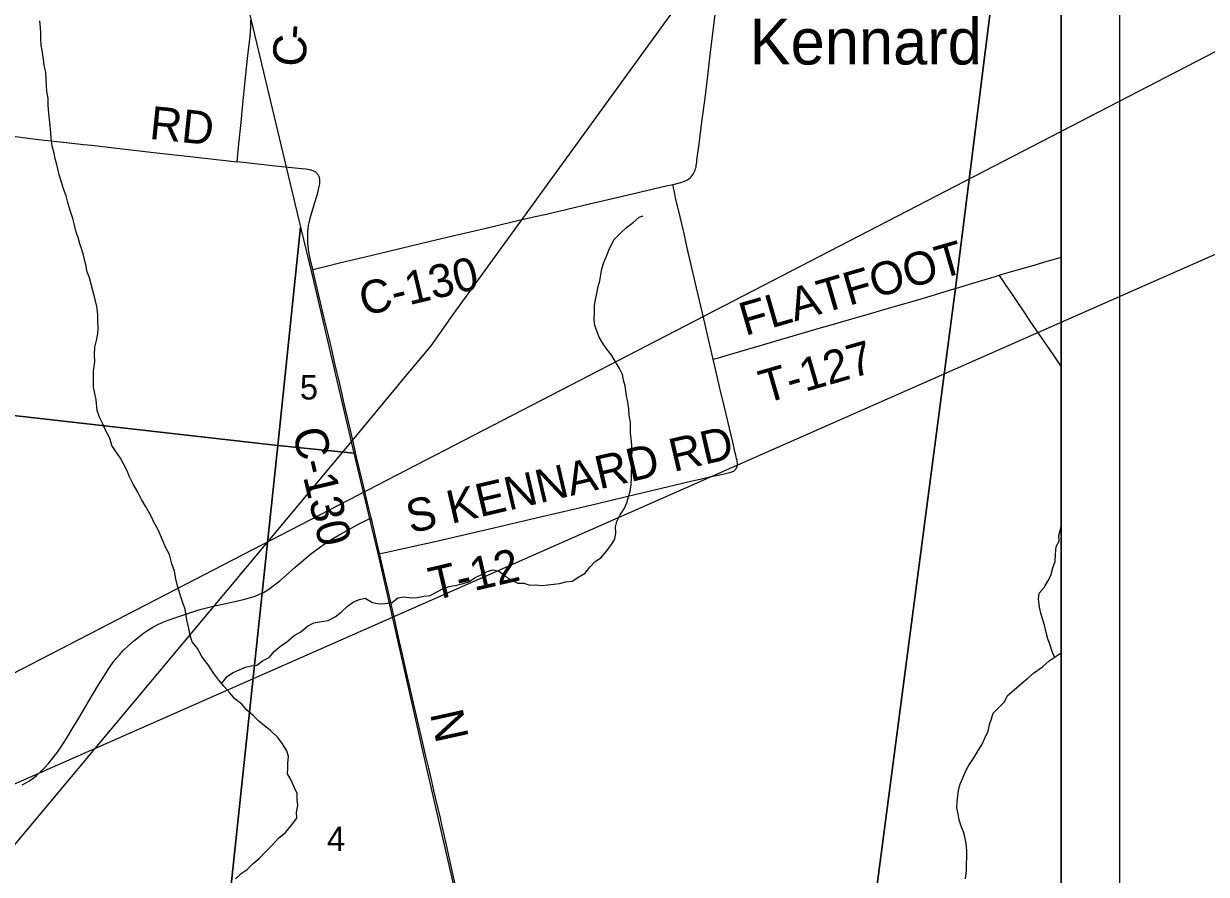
# Model space of a CAD drawing. Extents: x 831 to 1552, y 430 to 870.
# Drawn here: x 1046.09 to 1086.76, y 695.8 to 725.05 of the extents above; entities that cross this region are included whole.
import ezdxf

# ---------------------------------------------------------------- set-up
doc = ezdxf.new("R2010")
doc.units = 0
for name, color, linetype in [('GM_X_Corporation', 7, 'Continuous'), ('GM_X_County_Road', 7, 'Continuous'), ('GM_X_County_Road_Text', 7, 'Continuous'), ('GM_X_Minor_River', 7, 'Continuous'), ('GM_X_Rail_Line', 7, 'Continuous'), ('GM_X_Section_Text', 7, 'Continuous'), ('GM_X_Township_Road', 7, 'Continuous'), ('GM_X_Township_Road_Text', 7, 'Continuous'), ('GM_X_Unincorporated_Text', 7, 'Continuous'), ('SH_Data', 7, 'Continuous'), ('SH_Text', 7, 'Continuous')]:
    doc.layers.add(name, color=color, linetype=linetype)

msp = doc.modelspace()

# ---------------------------------------------------------------- linework, layer by layer
at = {"layer": 'GM_X_Corporation'}
msp.add_lwpolyline([(957.479, 781.045), (956.56, 771.006), (955.451, 760.717), (953.653, 740.871), (952.689, 730.885), (949.971, 703.401), (947.763, 681.071), (945.766, 658.183), (945.766, 650.938), (1069.909, 650.938), (1070.34, 654.531), (1072.813, 675.454), (1078.126, 715.958), (1081.227, 740.59), (1081.766, 744.853), (1081.766, 786.938)], dxfattribs=at)
for points in [[(1069.909, 650.938), (1081.766, 650.938), (1081.766, 744.853), (1081.227, 740.59), (1078.126, 715.958), (1072.813, 675.454), (1070.34, 654.531)], [(1036.878, 732.803), (1052.432, 731.297), (1052.759, 730.026), (1055.607, 718.06), (1054.834, 710.548), (1034.738, 712.834)], [(1056.005, 716.407), (1057.444, 710.279), (1054.834, 710.548), (1055.607, 718.06)], [(1034.738, 712.834), (1054.834, 710.548), (1052.831, 691.774), (1032.694, 693.772)], [(1054.834, 710.548), (1057.444, 710.279), (1058.309, 706.633), (1059.895, 699.645), (1061.888, 690.989), (1052.831, 691.774)]]:
    msp.add_lwpolyline(points, close=True, dxfattribs=at)
at = {"layer": 'GM_X_County_Road'}
for points in [[(1053.43, 720.304), (1053.489, 720.919), (1053.565, 721.652), (1053.631, 722.295), (1053.73, 723.309), (1053.791, 723.852), (1053.845, 724.334), (1053.873, 724.606), (1053.899, 724.929), (1053.905, 725.178)], [(1068.419, 719.528), (1068.685, 719.597), (1068.809, 719.634), (1068.864, 719.657), (1068.919, 719.685), (1068.967, 719.721), (1069.003, 719.75), (1069.04, 719.786), (1069.076, 719.827), (1069.109, 719.876), (1069.135, 719.921), (1069.159, 719.972), (1069.18, 720.024), (1069.197, 720.078), (1069.21, 720.121), (1069.219, 720.174), (1069.233, 720.274), (1069.242, 720.36), (1069.326, 720.996), (1069.414, 721.675), (1069.519, 722.489), (1069.614, 723.254), (1069.689, 723.883), (1069.77, 724.549), (1069.884, 725.449)], [(1056.029, 716.596), (1055.967, 716.862), (1055.921, 717.08), (1055.885, 717.3), (1055.873, 717.4), (1055.862, 717.509), (1055.856, 717.657), (1055.856, 717.792), (1055.862, 717.898), (1055.871, 718.001), (1055.887, 718.112), (1055.905, 718.208), (1055.941, 718.365), (1055.993, 718.556), (1056.11, 718.936), (1056.2, 719.234), (1056.232, 719.355), (1056.25, 719.437), (1056.263, 719.502), (1056.27, 719.555), (1056.273, 719.596), (1056.275, 719.631), (1056.273, 719.668), (1056.271, 719.697), (1056.268, 719.721), (1056.263, 719.745), (1056.255, 719.77), (1056.247, 719.794), (1056.237, 719.818), (1056.227, 719.837), (1056.213, 719.857), (1056.199, 719.877), (1056.186, 719.893), (1056.169, 719.909), (1056.132, 719.942), (1056.11, 719.957), (1056.089, 719.97), (1056.064, 719.983), (1056.041, 719.993), (1056.014, 720.002), (1055.991, 720.01), (1055.961, 720.017), (1055.928, 720.024), (1055.859, 720.036), (1055.778, 720.047), (1055.658, 720.064), (1055.536, 720.078), (1054.855, 720.146), (1053.43, 720.304)], [(1056.029, 716.596), (1056.212, 716.642), (1056.453, 716.704), (1056.996, 716.837), (1057.83, 717.039), (1058.361, 717.166), (1060.065, 717.577), (1060.997, 717.795), (1062.038, 718.036), (1062.884, 718.236), (1063.575, 718.394), (1064.108, 718.514), (1064.773, 718.672), (1065.548, 718.853), (1066.491, 719.076), (1067.313, 719.272), (1068.185, 719.473), (1068.419, 719.528)], [(1058.04, 708.056), (1057.918, 708.564), (1057.773, 709.158), (1057.54, 710.148), (1057.44, 710.583), (1057.292, 711.225), (1057.113, 711.986), (1056.956, 712.665), (1056.804, 713.318), (1056.683, 713.851), (1056.579, 714.287), (1056.423, 714.927), (1056.248, 715.664), (1056.029, 716.596)], [(1046.033, 698.877), (1046.19, 698.956), (1046.285, 699.016), (1046.378, 699.08), (1046.46, 699.144), (1046.535, 699.204), (1046.685, 699.337), (1046.817, 699.469), (1046.943, 699.608), (1047.086, 699.781), (1047.214, 699.95), (1047.356, 700.154), (1047.558, 700.468), (1047.817, 700.893), (1047.949, 701.118), (1048.188, 701.525), (1048.639, 702.283), (1048.819, 702.566), (1048.925, 702.734), (1049.033, 702.9), (1049.147, 703.062), (1049.268, 703.219), (1049.38, 703.35), (1049.516, 703.493), (1049.677, 703.648), (1049.872, 703.821), (1050.034, 703.954), (1050.212, 704.089), (1050.384, 704.209), (1050.531, 704.3), (1050.684, 704.381), (1050.852, 704.458), (1051.024, 704.528), (1051.293, 704.623), (1051.634, 704.738), (1052.011, 704.863), (1052.189, 704.917), (1052.333, 704.955), (1052.562, 705.011), (1053.253, 705.164), (1053.69, 705.263), (1053.895, 705.318), (1054.049, 705.369), (1054.2, 705.43), (1054.335, 705.496), (1054.455, 705.565), (1054.57, 705.64), (1054.72, 705.752), (1054.894, 705.894), (1055.091, 706.065), (1055.426, 706.361), (1055.791, 706.677), (1055.955, 706.808), (1056.262, 707.04), (1056.454, 707.176), (1056.629, 707.292), (1056.909, 707.452), (1057.559, 707.816), (1057.83, 707.955), (1058.04, 708.056)], [(1058.323, 706.828), (1058.243, 707.172), (1058.069, 707.936), (1058.04, 708.056)], [(1061.073, 694.835), (1060.978, 695.259), (1060.802, 696.022), (1060.658, 696.652), (1060.492, 697.405), (1060.418, 697.732), (1060.343, 698.059), (1060.196, 698.687), (1060.121, 699.001), (1060.016, 699.448), (1059.92, 699.859), (1059.759, 700.562), (1059.599, 701.252), (1059.507, 701.639), (1059.434, 701.954), (1059.313, 702.487), (1059.125, 703.311), (1059.017, 703.796), (1058.85, 704.535), (1058.736, 705.044), (1058.632, 705.504), (1058.458, 706.242), (1058.323, 706.828)]]:
    msp.add_lwpolyline(points, dxfattribs=at)
at = {"layer": 'GM_X_Minor_River'}
for points in [[(1054.171, 701.072), (1053.975, 701.279), (1053.764, 701.449), (1053.59, 701.648), (1053.348, 701.84), (1053.175, 702.04), (1052.987, 702.262), (1052.798, 702.477), (1052.633, 702.706), (1052.468, 702.959), (1052.22, 703.296), (1052.07, 703.563), (1051.889, 703.801), (1051.815, 704.014), (1051.771, 704.25), (1051.698, 704.555), (1051.64, 704.92), (1051.559, 705.134), (1051.492, 705.347), (1051.381, 705.72), (1051.323, 705.964), (1051.272, 706.223), (1051.183, 706.482), (1051.102, 706.794), (1050.982, 707.031), (1050.848, 707.328), (1050.714, 707.649), (1050.579, 707.893), (1050.467, 708.137), (1050.28, 708.458), (1050.137, 708.695), (1050.01, 708.947), (1049.86, 709.214), (1049.725, 709.466), (1049.644, 709.672), (1049.524, 709.916), (1049.419, 710.114), (1049.254, 710.344), (1049.119, 710.543), (1049.052, 710.794), (1048.888, 711.099), (1048.798, 711.32), (1048.701, 711.518), (1048.612, 711.747), (1048.585, 712.119), (1048.49, 712.553), (1048.487, 713.107), (1048.536, 713.425), (1048.523, 713.661), (1048.533, 713.934), (1048.589, 714.153), (1048.644, 714.388), (1048.646, 714.593), (1048.64, 714.828), (1048.635, 715.048), (1048.607, 715.322), (1048.556, 715.527), (1048.35, 716.318), (1048.275, 716.516), (1048.232, 716.76), (1048.144, 717.087), (1048.085, 717.285), (1048.018, 717.482), (1047.959, 717.695), (1047.9, 717.886), (1047.841, 718.121), (1047.775, 718.35), (1047.686, 718.631), (1047.612, 718.898), (1047.554, 719.133), (1047.464, 719.369), (1047.39, 719.605), (1047.309, 719.856), (1047.229, 720.214), (1047.177, 720.404), (1047.133, 720.601), (1047.075, 720.845), (1047.039, 721.111), (1047.026, 721.316), (1046.997, 721.536), (1046.956, 721.976), (1046.935, 722.235), (1046.93, 722.477), (1046.887, 722.728), (1046.873, 722.918), (1046.867, 723.13), (1046.847, 723.381), (1046.796, 723.617), (1046.767, 723.837), (1046.724, 724.126), (1046.696, 724.316), (1046.683, 724.543), (1046.677, 724.733), (1046.663, 724.923), (1046.65, 725.151)], [(1065.717, 715.365), (1065.749, 715.554), (1065.804, 715.774), (1065.845, 716.016), (1065.9, 716.213), (1065.932, 716.426), (1065.972, 716.623), (1066.043, 716.835), (1066.159, 717.114), (1066.23, 717.326), (1066.393, 717.636), (1066.623, 717.862), (1066.823, 718.042), (1067.053, 718.215), (1067.253, 718.395), (1067.39, 718.447)], [(1052.896, 702.366), (1053.097, 702.611), (1053.288, 702.746), (1053.502, 702.827), (1053.716, 702.924), (1053.915, 702.967), (1054.105, 702.996), (1054.297, 703.138), (1054.526, 703.258), (1054.711, 703.469), (1054.934, 703.656), (1055.125, 703.784), (1055.386, 704.009), (1055.616, 704.144), (1055.854, 704.331), (1056.068, 704.451), (1056.266, 704.479), (1056.556, 704.53), (1056.801, 704.656), (1057.008, 704.814), (1057.215, 705.009), (1057.437, 705.167), (1057.636, 705.256), (1057.835, 705.3), (1058.084, 705.153), (1058.312, 705.105), (1058.518, 705.111), (1058.762, 705.146), (1058.961, 705.304), (1059.16, 705.34), (1059.411, 705.307), (1059.624, 705.32), (1059.853, 705.364), (1060.066, 705.392), (1060.265, 705.489), (1060.495, 705.616), (1060.724, 705.697), (1060.968, 705.741), (1061.205, 705.799), (1061.395, 705.858), (1061.61, 706.008), (1061.816, 706.097), (1062.023, 706.217), (1062.237, 706.276), (1062.45, 706.213), (1062.661, 706.059), (1062.866, 705.912), (1063.085, 705.812), (1063.291, 705.817), (1063.496, 705.747), (1063.702, 705.752), (1063.915, 705.728), (1064.113, 705.756), (1064.319, 705.777), (1064.517, 705.806), (1064.738, 705.864), (1064.952, 705.885), (1065.174, 706.027), (1065.403, 706.162), (1065.558, 706.358), (1065.742, 706.561), (1065.941, 706.689), (1066.141, 706.922), (1066.303, 707.141), (1066.412, 707.33), (1066.452, 707.543), (1066.438, 707.748), (1066.486, 707.937), (1066.602, 708.164), (1066.733, 708.368), (1066.827, 708.572), (1066.889, 708.777), (1066.944, 708.966), (1066.977, 709.209), (1066.987, 709.444), (1066.996, 709.634), (1066.998, 709.87), (1066.993, 710.082), (1067.018, 710.325), (1067.005, 710.553), (1066.984, 710.774), (1066.955, 710.987), (1066.951, 711.336), (1066.908, 711.587), (1066.895, 711.807), (1066.866, 712.036), (1066.823, 712.256), (1066.772, 712.598), (1066.713, 712.796), (1066.685, 712.986), (1066.58, 713.2), (1066.445, 713.429), (1066.318, 713.643), (1066.137, 713.865), (1065.994, 714.079), (1065.874, 714.27), (1065.807, 714.46), (1065.733, 714.674), (1065.705, 714.864), (1065.715, 715.122), (1065.717, 715.365)], [(1081.535, 703.263), (1081.452, 703.461), (1081.385, 703.682), (1081.304, 703.896), (1081.245, 704.116), (1081.194, 704.368), (1081.12, 704.581), (1081.068, 704.779), (1081.017, 704.993), (1080.989, 705.274), (1081.014, 705.471), (1081.175, 705.668), (1081.307, 705.879), (1081.408, 706.076), (1081.479, 706.341), (1081.557, 706.561), (1081.574, 706.796), (1081.592, 707.069), (1081.693, 707.258), (1081.687, 707.456), (1081.75, 707.706), (1081.766, 707.783)], [(1080.153, 702.142), (1080.399, 702.36), (1080.621, 702.549), (1080.813, 702.714), (1081.127, 702.932), (1081.358, 703.143), (1081.766, 703.419)], [(1078.472, 695.646), (1078.505, 695.935), (1078.507, 696.156), (1078.524, 696.369), (1078.518, 696.567), (1078.505, 696.787), (1078.469, 697.039), (1078.41, 697.26), (1078.321, 697.451), (1078.262, 697.672), (1078.226, 697.885), (1078.174, 698.091), (1078.184, 698.289), (1078.209, 698.502), (1078.233, 698.692), (1078.288, 698.897), (1078.39, 699.139), (1078.475, 699.336), (1078.583, 699.533), (1078.784, 699.843), (1078.916, 700.062), (1079.032, 700.251), (1079.14, 700.478), (1079.257, 700.721), (1079.305, 700.956), (1079.367, 701.146), (1079.43, 701.343), (1079.63, 701.554), (1079.822, 701.735), (1079.923, 701.947), (1080.153, 702.142)], [(1053.368, 695.65), (1053.568, 695.831), (1053.775, 695.966), (1053.982, 696.169), (1054.182, 696.342), (1054.412, 696.583), (1054.62, 696.794), (1054.85, 697.043), (1055.096, 697.238), (1055.296, 697.487), (1055.481, 697.736), (1055.475, 697.926), (1055.515, 698.162), (1055.494, 698.36), (1055.489, 698.58), (1055.392, 698.794), (1055.287, 699.038), (1055.16, 699.253), (1055.177, 699.443), (1055.171, 699.64), (1055.196, 699.853), (1055.137, 700.044), (1054.987, 700.288), (1054.829, 700.503), (1054.58, 700.741), (1054.368, 700.903), (1054.171, 701.072)]]:
    msp.add_lwpolyline(points, dxfattribs=at)
at = {"layer": 'GM_X_Rail_Line'}
msp.add_lwpolyline([(1019.767, 662.513), (1021.761, 666.57), (1022.769, 668.517), (1023.711, 670.015), (1024.761, 671.556), (1025.705, 672.853), (1026.7, 674.233), (1031.154, 679.565), (1036.15, 685.527), (1045.521, 696.507), (1057.393, 710.715), (1059.26, 712.976), (1060.098, 713.979), (1060.856, 715.052), (1068.102, 725.035), (1069.841, 727.406), (1071.639, 730.006), (1075.116, 734.935), (1078.227, 739.322), (1079.494, 741.028), (1080.443, 742.199), (1081.307, 743.182), (1081.766, 743.624)], dxfattribs=at)
at = {"layer": 'GM_X_Township_Road'}
for points in [[(1042.122, 721.589), (1043.325, 721.454), (1043.498, 721.435), (1043.708, 721.412), (1044.7, 721.295), (1045.64, 721.192), (1046.604, 721.075), (1047.548, 720.97), (1048.152, 720.903), (1048.424, 720.874), (1048.72, 720.839), (1049.288, 720.772), (1049.893, 720.703), (1050.461, 720.639), (1051.289, 720.544), (1051.709, 720.497), (1053.43, 720.304)], [(1069.798, 713.512), (1069.674, 714.055), (1069.477, 714.902), (1069.184, 716.161), (1068.91, 717.348), (1068.797, 717.832), (1068.66, 718.413), (1068.509, 719.062), (1068.477, 719.207), (1068.456, 719.311), (1068.439, 719.403), (1068.427, 719.48), (1068.419, 719.528)], [(1079.636, 716.407), (1079.742, 716.441), (1080.063, 716.533), (1080.755, 716.727), (1081.136, 716.838), (1081.361, 716.907), (1081.695, 717.004), (1081.766, 717.025)], [(1078.13, 715.947), (1078.614, 716.095), (1079.032, 716.216), (1079.459, 716.348), (1079.636, 716.407)], [(1081.766, 713.265), (1081.708, 713.352), (1081.66, 713.424), (1081.542, 713.598), (1081.374, 713.844), (1081.087, 714.265), (1080.7, 714.828), (1080.516, 715.108), (1080.275, 715.47), (1080.022, 715.839), (1079.876, 716.055), (1079.75, 716.24), (1079.636, 716.407)], [(1069.798, 713.512), (1069.984, 713.566), (1070.329, 713.668), (1071.38, 713.97), (1072.549, 714.315), (1073.527, 714.6), (1073.981, 714.73), (1074.41, 714.855), (1074.932, 715.011), (1075.207, 715.089), (1075.709, 715.233), (1076.306, 715.403), (1076.64, 715.501), (1077.151, 715.653), (1077.591, 715.785), (1078.079, 715.932), (1078.13, 715.947)], [(1058.323, 706.828), (1058.475, 706.861), (1059.447, 707.073), (1060.235, 707.251), (1061.12, 707.451), (1062.451, 707.759), (1063.709, 708.057), (1064.507, 708.247), (1065.632, 708.512), (1066.442, 708.703), (1067.107, 708.861), (1068.026, 709.08), (1068.701, 709.245), (1068.931, 709.298), (1069.136, 709.345), (1069.353, 709.395), (1069.675, 709.464), (1070.027, 709.536), (1070.218, 709.58), (1070.318, 709.603), (1070.372, 709.617), (1070.422, 709.631), (1070.467, 709.65), (1070.504, 709.669), (1070.537, 709.691), (1070.56, 709.712), (1070.58, 709.737), (1070.606, 709.782), (1070.62, 709.817), (1070.629, 709.856), (1070.632, 709.89), (1070.632, 709.934), (1070.628, 709.983), (1070.62, 710.035), (1070.606, 710.097), (1070.593, 710.15), (1070.578, 710.215), (1070.56, 710.292), (1070.471, 710.667), (1070.185, 711.868), (1070.021, 712.566), (1069.876, 713.171), (1069.798, 713.512)]]:
    msp.add_lwpolyline(points, dxfattribs=at)
at = {"layer": 'SH_Data'}
for p, q in [((1083.766, 788.938), (1083.766, 648.938)), ((1081.766, 786.938), (1081.766, 650.938))]:
    msp.add_line(p, q, dxfattribs=at)
at = {"layer": 'SH_Text'}
msp.add_lwpolyline([(995.67, 676.817), (1119.5, 731.442), (1119.5, 740.878)], close=True, dxfattribs=at)

# ---------------------------------------------------------------- texts
at = {"layer": 'GM_X_County_Road_Text'}
for s, height, rotation, p in [('-', 1.136, 85.9539, (1055.843, 724.49)), ('C', 1.136, 84.6098, (1055.753, 723.532)), ('C-130', 1.1364, 13.4431, (1057.784, 714.998)), ('C-130', 1.1364, 283.3598, (1055.324, 711.035)), ('N', 1.136, 282.4233, (1060.058, 701.33))]:
    msp.add_text(s, height=height, rotation=rotation, dxfattribs=at).set_placement(p)
at = {"layer": 'GM_X_Section_Text'}
for s, p in [('5', (1055.588, 712.129)), ('4', (1056.521, 696.608))]:
    msp.add_text(s, height=0.837, rotation=0, dxfattribs=at).set_placement(p)
at = {"layer": 'GM_X_Township_Road_Text'}
for s, height, rotation, p in [('RD', 1.1364, 354.1407, (1050.388, 721.095)), ('FLATFOOT', 1.1364, 16.1645, (1070.898, 714.314)), ('T-127', 1.1364, 16.1375, (1071.58, 711.988)), ('S KENNARD RD', 1.13636, 13.1549, (1059.392, 707.521)), ('T-12', 1.1364, 13.1803, (1060.179, 705.212))]:
    msp.add_text(s, height=height, rotation=rotation, dxfattribs=at).set_placement(p)
at = {"layer": 'GM_X_Unincorporated_Text'}
msp.add_text('Kennard', height=1.5795, rotation=0, dxfattribs=at).set_placement((1071.054, 723.65))

doc.saveas('drawing.dxf')
